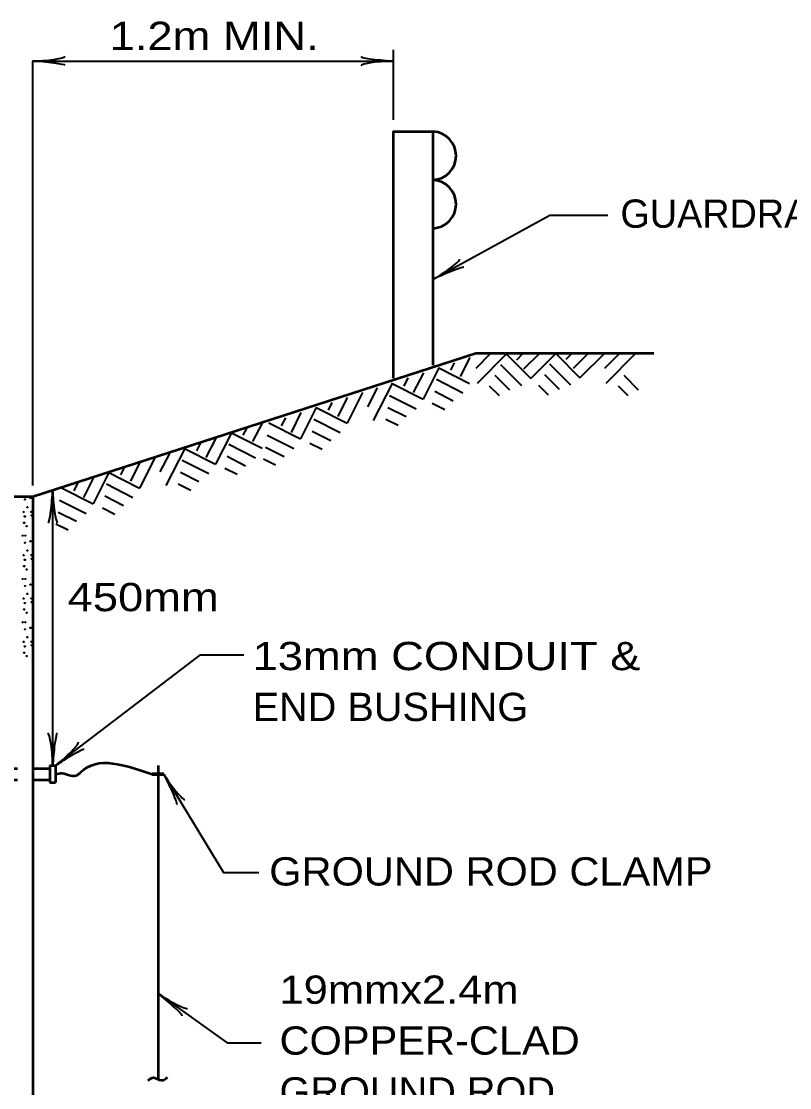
# Model space of a CAD drawing. Extents: x -46 to 809, y -15 to 529.
# Drawn here: x 114.1 to 195.7, y 199.1 to 312.3 of the extents above; entities that cross this region are included whole.
import ezdxf
from ezdxf.enums import TextEntityAlignment as Align

# ---------------------------------------------------------------- set-up
doc = ezdxf.new("R2010")
doc.units = 0
doc.header["$LTSCALE"] = 1.2
doc.linetypes.add('LONG_DASHED', pattern=[7.5, 6, -1.5])
doc.layers.add('1', color=7, linetype='Continuous', lineweight=35)

msp = doc.modelspace()

# ---------------------------------------------------------------- linework, layer by layer
at = {"layer": '1'}
for p, q in [((153.611, 301.898), (153.611, 309.327)), ((161.71, 276.645), (160.678, 274.629)), ((163.922, 277.071), (162.338, 275.487)), ((165.65, 277.071), (162.482, 273.903)), ((165.53, 277.071), (168.194, 274.431)), ((167.353, 277.071), (166.681, 276.375)), ((169.106, 277.071), (167.425, 275.415)), ((170.834, 277.071), (168.194, 274.431)), ((170.834, 277.071), (173.401, 274.503)), ((172.537, 277.071), (171.913, 276.447)), ((174.29, 277.071), (172.681, 275.487)), ((175.994, 277.071), (173.401, 274.503)), ((177.602, 277.071), (175.994, 275.487)), ((179.305, 277.071), (176.138, 273.903)), ((158.422, 275.565), (156.742, 272.229)), ((158.422, 275.565), (161.686, 273.909)), ((160.054, 276.093), (159.645, 275.301)), ((164.954, 275.919), (167.186, 273.687)), ((170.186, 275.991), (172.418, 273.759)), ((155.133, 274.485), (154.702, 273.621)), ((156.79, 275.037), (155.71, 272.925)), ((158.157, 274.341), (160.966, 272.901)), ((164.377, 274.767), (165.938, 273.207)), ((169.633, 274.839), (171.194, 273.279)), ((178.058, 274.767), (179.594, 273.207)), ((150.334, 272.949), (148.678, 269.685)), ((151.87, 273.429), (150.838, 271.413)), ((153.502, 273.957), (151.462, 269.973)), ((153.382, 273.933), (156.742, 272.229)), ((157.99, 273.069), (159.934, 272.061)), ((163.778, 273.639), (164.834, 272.631)), ((169.01, 273.711), (170.042, 272.679)), ((177.458, 273.639), (178.49, 272.631)), ((147.046, 271.869), (146.662, 271.077)), ((148.702, 272.421), (147.694, 270.405)), ((153.19, 272.637), (156.022, 271.221)), ((157.726, 271.797), (159.046, 271.149)), ((143.781, 270.813), (142.726, 268.701)), ((145.413, 271.341), (143.734, 268.005)), ((145.413, 271.341), (148.678, 269.685)), ((153.022, 271.365), (154.966, 270.381)), ((139.685, 269.754), (138.653, 267.738)), ((140.374, 269.709), (143.734, 268.005)), ((142.126, 270.261), (141.694, 269.397)), ((145.15, 270.117), (147.958, 268.677)), ((152.781, 270.117), (154.102, 269.469)), ((136.397, 268.674), (134.717, 265.338)), ((136.397, 268.674), (139.661, 267.018)), ((138.029, 269.202), (137.621, 268.41)), ((140.181, 268.413), (143.013, 266.997)), ((144.982, 268.845), (146.95, 267.837)), ((133.109, 267.594), (132.677, 266.73)), ((134.765, 268.146), (133.685, 266.034)), ((136.133, 267.45), (138.941, 266.01)), ((144.742, 267.573), (146.037, 266.925)), ((128.309, 266.058), (126.653, 262.794)), ((129.845, 266.538), (128.813, 264.522)), ((131.477, 267.066), (129.437, 263.082)), ((131.357, 267.042), (134.717, 265.338)), ((135.965, 266.178), (137.909, 265.17)), ((140.013, 267.141), (141.982, 266.157)), ((125.021, 264.978), (124.637, 264.186)), ((126.677, 265.53), (125.669, 263.514)), ((131.165, 265.746), (133.997, 264.33)), ((139.798, 265.893), (141.094, 265.245)), ((121.757, 263.922), (120.701, 261.81)), ((123.389, 264.45), (121.709, 261.114)), ((123.389, 264.45), (126.653, 262.794)), ((130.997, 264.474), (132.941, 263.49)), ((135.701, 264.906), (137.021, 264.258)), ((118.349, 262.818), (121.709, 261.114)), ((120.101, 263.37), (119.669, 262.506)), ((123.125, 263.226), (125.933, 261.786)), ((130.757, 263.226), (132.077, 262.578)), ((117.425, 233.322), (117.425, 262.57)), ((122.957, 261.954), (124.925, 260.946)), ((118.157, 261.522), (120.989, 260.106)), ((122.717, 260.682), (124.013, 260.034)), ((117.989, 260.25), (119.957, 259.266)), ((117.773, 259.002), (119.069, 258.354))]:
    msp.add_line(p, q, dxfattribs=at)
at = {"layer": '1', "lineweight": 53}
for p, q in [((157.835, 275.839), (157.835, 300.655)), ((115.301, 261.882), (162.338, 277.119)), ((162.338, 277.119), (181.25, 277.119)), ((85.061, 261.882), (115.301, 261.882)), ((117.125, 233.322), (117.125, 231.522)), ((117.125, 233.322), (117.725, 233.322)), ((117.725, 233.322), (117.725, 231.522)), ((128.621, 233.322), (128.621, 200.058)), ((115.301, 233.034), (117.125, 233.034)), ((115.301, 231.81), (117.125, 231.81)), ((117.125, 231.522), (117.725, 231.522))]:
    msp.add_line(p, q, dxfattribs=at)
at = {"layer": '1', "linetype": 'LONG_DASHED', "lineweight": 53}
for p, q in [((106.493, 233.034), (115.301, 233.034)), ((106.493, 231.81), (115.301, 231.81))]:
    msp.add_line(p, q, dxfattribs=at)
at = {"layer": '1', "lineweight": 70}
msp.add_line((127.997, 232.41), (129.221, 232.41), dxfattribs=at)
at = {"layer": '1'}
for points in [[(115.301, 263.082), (115.301, 308.127), (153.611, 308.127)], [(157.835, 284.966), (170.216, 291.778), (176.356, 291.778)], [(117.725, 233.322), (133.121, 245.079), (137.726, 245.079)], [(129.221, 232.41), (135.57, 221.969), (139.311, 221.969)], [(128.621, 209.145), (135.957, 203.904), (139.569, 203.904)]]:
    msp.add_lwpolyline(points, dxfattribs=at)
at = {"layer": '1', "lineweight": 53}
for points in [[(153.611, 274.471), (153.611, 300.655), (157.835, 300.655)], [(115.301, 261.882), (115.301, 162), (115.301, 139.698), (85.061, 139.698), (85.061, 157.089), (85.043, 157.097)]]:
    msp.add_lwpolyline(points, dxfattribs=at)
at = {"layer": '1'}
for centre in [(114.477, 261.587), (115.07, 261.742), (114.734, 260.753), (114.333, 260.256), (114.461, 259.775), (115.167, 260.272), (115.182, 259.887), (114.397, 259.102), (114.67, 258.749), (114.237, 257.738), (114.477, 256.991), (114.509, 257.738), (115.07, 257.145), (114.734, 256.157), (114.333, 255.66), (114.461, 255.179), (115.167, 255.676), (115.182, 255.291), (114.397, 254.505), (114.67, 254.152), (114.237, 253.142), (114.509, 253.142), (115.07, 252.549), (114.477, 252.394), (114.734, 251.56), (114.333, 251.063), (114.461, 250.582), (115.167, 251.079), (115.182, 250.694), (114.397, 249.909), (114.67, 249.556), (114.237, 248.545), (114.509, 248.545), (115.07, 247.952), (114.477, 247.798), (114.734, 246.964), (114.333, 246.467), (114.461, 245.986), (115.167, 246.483), (115.182, 246.098), (114.397, 245.312), (114.67, 244.959)]:
    msp.add_circle(centre, 0.032, dxfattribs=at)
at = {"layer": '1', "lineweight": 53}
for centre in [(157.681, 298.074), (157.681, 292.933)]:
    msp.add_arc(centre, 2.575, 273.47141, 86.52859, dxfattribs=at)
at = {"layer": '1', "lineweight": 40}
for centre, major_axis, ratio, start_param, end_param in [((116.646, 307.873), (-2.108, 0.211), 0.07063, 3.1407148, 5.41811), ((116.646, 307.873), (-2.108, 0.211), 0.07063, 3.1407148, 5.41811), ((116.611, 308.459), (-2.143, -0.187), 0.122415, 0.8963533, 3.1415927), ((116.611, 308.459), (-2.143, -0.187), 0.122415, 0.8963533, 3.1415927), ((152.291, 307.805), (2.143, 0.187), 0.122415, 0.8963533, 3.1415927), ((152.256, 308.391), (2.108, -0.211), 0.07063, 3.1407148, 5.41811), ((158.822, 285.888), (-1.787, -1.197), 0.122415, 0.8963533, 3.1415927), ((158.822, 285.888), (-1.787, -1.197), 0.122415, 0.8963533, 3.1415927), ((159.135, 285.391), (1.948, 0.831), 0.07063, 6.2823074, 8.5597026), ((159.135, 285.391), (1.948, 0.831), 0.07063, 6.2823074, 8.5597026), ((117.171, 261.225), (0.211, 2.108), 0.07063, 3.1407148, 5.41811), ((117.171, 261.225), (0.211, 2.108), 0.07063, 3.1407148, 5.41811), ((117.757, 261.26), (-0.187, 2.143), 0.122415, 0.8963533, 3.1415927), ((117.757, 261.26), (-0.187, 2.143), 0.122415, 0.8963533, 3.1415927), ((117.094, 234.631), (0.187, -2.143), 0.122415, 0.8963533, 3.1415927), ((117.679, 234.666), (-0.211, -2.108), 0.07063, 3.1407148, 5.41811), ((118.565, 234.38), (-1.589, -1.449), 0.122415, 0.8963533, 3.1415927), ((118.948, 233.936), (1.803, 1.112), 0.07063, 6.2823074, 8.5597026), ((129.703, 231.129), (0.915, -1.91), 0.07063, 6.2823074, 8.5597026), ((130.185, 231.463), (-1.273, 1.734), 0.122415, 0.8963533, 3.1415927), ((129.568, 208.157), (1.592, -1.397), 0.07063, 6.2823074, 8.5597026), ((129.88, 208.654), (-1.852, 1.093), 0.122415, 0.8963533, 3.1415927)]:
    msp.add_ellipse(centre, major_axis=major_axis, ratio=ratio, start_param=start_param, end_param=end_param, dxfattribs=at)
at = {"layer": '1', "lineweight": 53}
for points in [[(117.725, 232.41), (118.421, 232.53), (119.309, 232.266), (120.125, 232.386), (120.389, 232.626), (127.997, 232.41)], [(127.517, 199.89), (128.141, 200.202), (128.933, 199.914), (129.173, 199.938), (129.629, 200.25)]]:
    msp.add_spline(points, degree=3, dxfattribs=at)

# ---------------------------------------------------------------- texts
at = {"layer": '1'}
for s, width, p in [('1.2m MIN.', 1.2, (134.567, 309.303)), ('450mm', 1.2, (127.032, 249.722)), ('GROUND ROD CLAMP', 1.1, (163.949, 220.598))]:
    msp.add_text(s, height=3, dxfattribs=dict(at, width=width)).set_placement(p, align=Align.CENTER)
msp.add_text('GUARDRAIL', height=3, dxfattribs=at).set_placement((189.403, 290.431), align=Align.CENTER)
for s, width, p in [('13mm CONDUIT &', 1.2, (138.647, 243.461)), ('END BUSHING', 1.05, (138.647, 238.061)), ('19mmx2.4m', 1.15, (141.506, 208.04)), ('COPPER-CLAD', 1.1, (141.506, 202.639)), ('GROUND ROD', 1.05, (141.506, 197.24))]:
    msp.add_text(s, height=3, dxfattribs=dict(at, width=width)).set_placement(p)

doc.saveas('drawing.dxf')
